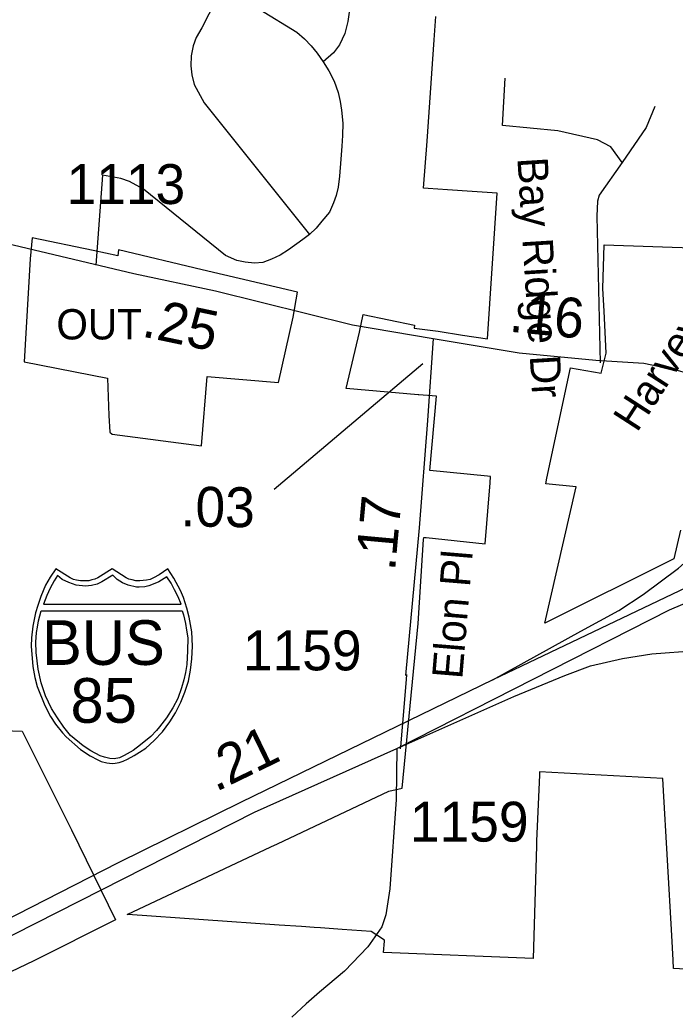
# Model space of a CAD drawing. Extents: x 1662474 to 1856135, y 779280 to 917889.
# Drawn here: x 1719678 to 1721731, y 803792 to 806900 of the extents above; entities that cross this region are included whole.
import ezdxf

# ---------------------------------------------------------------- set-up
doc = ezdxf.new("R2010")
doc.units = 0
for name, color, linetype in [('Exist Boundary Political City Limit New', 7, 'Continuous'), ('Exist Boundary Political City Limit New Hole', 7, 'Continuous'), ('Exist Road Non-System Type 51', 7, 'Continuous'), ('Exist Road Non-System Type 51 Label', 7, 'Continuous'), ('Exist Road Primary Interstate Divided Center Attributed', 7, 'Continuous'), ('Exist Road Primary Interstate Mileage Hundredths English Label', 7, 'Continuous'), ('Exist Road Primary Interstate Ramp 1 Lane Attributed', 7, 'Continuous'), ('Exist Road Primary Interstate Shield CELL', 7, 'Continuous'), ('Exist Road Primary Interstate Shield Number Label', 7, 'Continuous'), ('Exist Road Secondary Mileage Hundredths English Label', 7, 'Continuous'), ('Exist Road Secondary Mileage Tenths English Label', 7, 'Continuous'), ('Exist Road Secondary Type 51 Attributed', 7, 'Continuous'), ('Exist Road Secondary Type 51 Label', 7, 'Continuous'), ('Exist Road Secondary Type 51 Number Label', 7, 'Continuous'), ('Map Preparation Boundary City Limit Buffer Line', 7, 'Continuous')]:
    doc.layers.add(name, color=color, linetype=linetype)

msp = doc.modelspace()

# ---------------------------------------------------------------- linework, layer by layer
at = {"layer": 'Exist Boundary Political City Limit New'}
for points in [[(1721173.6, 806356.1), (1721094.4, 806361.4), (1721017.2, 806366.7), (1720957, 806370.8), (1720942.1, 806372.2), (1720953.6, 806519.4), (1720967.9, 806731.8), (1720975.4, 806837.1), (1720980.6, 806910.2)], [(1722137.9, 803903.6), (1721725.5, 803926.3), (1721724.1, 803951.8), (1721719.8, 804029), (1721692.8, 804502.2), (1721691.6, 804521.8), (1721305.9, 804542.8), (1721305.4, 804533.2), (1721296.5, 804325.5), (1721296.4, 804322.4), (1721296, 804310.5), (1721285.6, 803957.2), (1720816.9, 803975.8), (1720820.4, 804012.2), (1720820.6, 804014.4), (1720778, 804042.1), (1720687, 804048.5), (1720619.2, 804053.2), (1720599.4, 804054.6), (1720560.4, 804057.4), (1720490.5, 804062.2), (1720015.6, 804095.6), (1720013.9, 804095.7), (1720464.4, 804307.7), (1720484.8, 804317.2), (1720834.2, 804481.7), (1720875.6, 804490.9), (1720926, 805007.3), (1720939.5, 805221.9), (1720942.6, 805271.2), (1720943, 805277.5), (1720950.5, 805276.7), (1721135.8, 805257.6), (1721140.9, 805321.3), (1721147, 805398.5), (1721148.9, 805421.7), (1721151, 805448.7), (1721152.6, 805468.3), (1721142.9, 805469.2), (1720961.9, 805486.9), (1720982.8, 805720.5), (1720928.1, 805724.4), (1720925.9, 805724.6), (1720700.2, 805744.1), (1720741.5, 805920.8), (1720753.4, 805975.6), (1720914, 805942.7), (1720913, 805932.7), (1720988.1, 805924.1), (1721064.2, 805911.5), (1721143.1, 805899.6), (1721173.6, 806356.1)], [(1721747.5, 805300.2), (1721726.5, 805210.4), (1721322.8, 805008), (1721420.6, 805435.9), (1721325.1, 805445.7), (1721328.8, 805462.7), (1721402.4, 805808.8), (1721499.1, 805792.4), (1721514.5, 805855.2), (1721509.1, 805964.4), (1721508, 805985.9), (1721504.5, 806057.5), (1721508.1, 806194.1), (1721966.2, 806178.8)], [(1718688.2, 803734.9), (1719498.1, 804134.4), (1718974.8, 804180.6), (1718997.4, 804506.2), (1719004, 804695.2), (1719269.6, 804685.4), (1719533.6, 804675.3), (1719685.4, 804669.5), (1719839.9, 804360.9), (1719976.9, 804078.1), (1719721.5, 803950.2), (1719294.9, 803746.4)]]:
    msp.add_lwpolyline(points, dxfattribs=at)
at = {"layer": 'Exist Boundary Political City Limit New Hole'}
msp.add_lwpolyline([(1719952, 805775.9), (1719956.2, 805659.5), (1719959.2, 805607.2), (1719966.6, 805601.2), (1720246.6, 805564.1), (1720264.6, 805781.8), (1720487.8, 805762.5), (1720534.1, 805967.9), (1720547.9, 806046.1), (1720249.2, 806116.4), (1719986.4, 806178.3), (1719985.1, 806159.8), (1719907, 806176.2), (1719716.5, 806215.9), (1719709.8, 806150.5), (1719690.9, 805828.1), (1719952, 805775.9)], dxfattribs=at)
at = {"layer": 'Exist Road Non-System Type 51'}
for p, q in [((1720889.1, 804847.4), (1720887.8, 804831.4)), ((1720887.8, 804831.4), (1720875.1, 804682)), ((1720875.1, 804682), (1720870.1, 804621.1))]:
    msp.add_line(p, q, dxfattribs=at)
for points in [[(1720515.4, 807450.8), (1720653.4, 807336.2), (1720681.5, 807302.4), (1720697.5, 807276.2), (1720708.5, 807252.4), (1720719.2, 807218.7), (1720724, 807192.8), (1720710.1, 806930.5), (1720705.1, 806894), (1720695.6, 806856.2), (1720678.9, 806821.1), (1720660.5, 806796.2), (1720628.4, 806768.1)], [(1720314, 807004.5), (1720247.6, 806874.4), (1720230.6, 806843.9), (1720221.1, 806817.7), (1720214.9, 806786.4), (1720213.5, 806754.9), (1720216.4, 806726.9), (1720224.2, 806696.7), (1720255.5, 806639.2), (1720585.1, 806226.9)], [(1720314, 807004.5), (1720545.8, 806861), (1720569.4, 806839.8), (1720589.9, 806818.4), (1720609.2, 806795.6), (1720628.4, 806768.1)], [(1720628.4, 806768.1), (1720645.5, 806740), (1720662.4, 806707.2), (1720675.4, 806672.2), (1720680.9, 806643.7), (1720685.4, 806616.1), (1720689.6, 806575.4), (1720688.9, 806537.1), (1720686.8, 806503.2), (1720683, 806463.1), (1720679.4, 806409.9), (1720674.9, 806374.7), (1720668.9, 806349.4), (1720660.1, 806325.6), (1720648.1, 806297.2), (1720624.2, 806268.1), (1720606.1, 806246.9), (1720585.1, 806226.9)], [(1721564.6, 806452.1), (1721529.2, 806501.4), (1721487.8, 806523.7), (1721363.6, 806551.2), (1721189.6, 806567.9), (1721198, 806716.6)], [(1721666.8, 806628.4), (1721639.4, 806562.2), (1721564.6, 806452.1)], [(1721564.6, 806452.1), (1721493, 806349.9), (1721487.5, 806330.9), (1721484.9, 806283.9), (1721495.6, 805824.2)], [(1720585.1, 806226.9), (1720564.6, 806211.4), (1720519.2, 806178.4), (1720493.5, 806162.4), (1720466.5, 806148.9), (1720438.6, 806139.2), (1720412.6, 806137.1), (1720383.4, 806139.8), (1720357.9, 806145.2), (1720321.6, 806160.8), (1720064.9, 806368.9), (1720021.4, 806393.2), (1719994.4, 806402.4), (1719936.4, 806412.9), (1719915.4, 806130.2)], [(1720870.1, 804621.1), (1720869.7, 804615)]]:
    msp.add_lwpolyline(points, dxfattribs=at)
at = {"layer": 'Exist Road Primary Interstate Divided Center Attributed'}
for points in [[(1722330.3, 805407), (1722186.6, 805332.3), (1721766.7, 805120.7), (1721159.6, 804831)], [(1720858.9, 804615.4), (1721713.2, 805050.4), (1721754.9, 805068.5), (1721854.3, 805114.4), (1722372.7, 805371.9)], [(1721159.6, 804831), (1720371, 804447.9), (1719985.3, 804257.2), (1719529, 804024.4), (1719223, 803873.5), (1718752.7, 803628.3), (1718585.1, 803541), (1718467.1, 803468.6)], [(1718437.4, 803380.4), (1718560.3, 803462.7), (1718798.4, 803604.1), (1719011.6, 803703.7), (1719282.9, 803844.8), (1719520.9, 803963.7), (1720413, 804416.2), (1720858.9, 804615.4)]]:
    msp.add_lwpolyline(points, dxfattribs=at)
at = {"layer": 'Exist Road Primary Interstate Ramp 1 Lane Attributed'}
for points in [[(1721159.6, 804831), (1721435.7, 804983.7), (1721554.5, 805048.2), (1721630.9, 805098), (1721740.7, 805180.7), (1721849.3, 805276.8), (1721991.4, 805435.3), (1722069.5, 805543.9), (1722105.7, 805586.9)], [(1720858.9, 804615.4), (1721225.8, 804778.9), (1721385.4, 804844.6), (1721465.7, 804875.1), (1721565.3, 804897.7), (1721658.1, 804912.4), (1721796.2, 804922.6), (1721910.5, 804917), (1722055.9, 804898.9), (1722143, 804889.8), (1722198.5, 804888.7), (1722257.3, 804892.1), (1722310.5, 804904.5), (1722360.3, 804923.8), (1722466.1, 804975.8), (1722528.3, 805020), (1722646, 805147.8)]]:
    msp.add_lwpolyline(points, dxfattribs=at)
at = {"layer": 'Exist Road Primary Interstate Shield CELL'}
for points in [[(1719966.5, 804568.6), (1719975.9, 804569.5), (1719988.7, 804572), (1720001.1, 804576.1), (1720015.2, 804582.3), (1720036, 804593.9), (1720052.8, 804603.7), (1720072.1, 804616.7), (1720098.2, 804640.4), (1720124.3, 804667.8), (1720147.3, 804698.8), (1720165.5, 804727.9), (1720181.6, 804761), (1720195, 804791.9), (1720205.7, 804827.2), (1720212.7, 804861.5), (1720216.3, 804897.2), (1720218.7, 804936.8), (1720216, 804981.3), (1720208.3, 805026.9), (1720201, 805055.2), (1720190, 805089.1), (1720181, 805110.8), (1720160.1, 805149.3), (1720141.4, 805178.9), (1720114.2, 805159.7), (1720096.4, 805150.3), (1720085.6, 805145.4), (1720074.4, 805143.2), (1720053.9, 805140.7), (1720041, 805141.3), (1720029.1, 805144), (1720018.9, 805146.2), (1720010.7, 805150.3), (1719966.5, 805178.9), (1719922.2, 805150.3), (1719912.9, 805146), (1719903.4, 805144), (1719894.3, 805141.5), (1719879.1, 805140.7), (1719867.5, 805141.1), (1719855.7, 805143.2), (1719846.3, 805145.2), (1719835.8, 805150.3), (1719790.7, 805178.9), (1719772.9, 805153.1), (1719758.5, 805127.7), (1719743.1, 805091.8), (1719733.6, 805064), (1719726.8, 805041.1), (1719718.4, 804999.1), (1719714.1, 804962.6), (1719713.4, 804936.8), (1719718.1, 804872.2), (1719725.1, 804837.9), (1719732.4, 804810.1), (1719756.2, 804750.1), (1719774.2, 804716.4), (1719789.6, 804692.3), (1719811.2, 804665.1), (1719822.9, 804652.1), (1719867.7, 804613), (1719897.6, 804592.5), (1719921.5, 804579.6), (1719932.7, 804575.4), (1719950.3, 804570.5)], [(1719796, 805158.1), (1719785.1, 805141.2), (1719772.4, 805118.4), (1719762.2, 805094.7), (1719751.9, 805068.5), (1720183.4, 805068.4), (1720173.4, 805090.8), (1720162.6, 805113.3), (1720151.4, 805133.9), (1720137.7, 805153.8), (1720113.5, 805138.5), (1720095.8, 805130.2), (1720081.7, 805125.3), (1720069.7, 805122.6), (1720051.1, 805121.1), (1720042.8, 805121.6), (1720016.8, 805127.5), (1719999.3, 805134.7), (1719982.6, 805145.8), (1719969, 805158.6), (1719934.8, 805137.9), (1719919.7, 805131.2), (1719902.2, 805126.7), (1719883.2, 805124.3), (1719853.7, 805127.5), (1719830.7, 805135.5), (1719810.8, 805145.8)], [(1720186, 805047.1), (1720190.6, 805034.9), (1720197, 805007.8), (1720200.3, 804987), (1720203.7, 804963), (1720202.5, 804921.9), (1720200.5, 804879.3), (1720196.6, 804854.1), (1720191.4, 804831.1), (1720184.2, 804805.7), (1720172.7, 804771.9), (1720156.8, 804743.2), (1720136.9, 804711.4), (1720115.4, 804683.5), (1720106.1, 804671.9), (1720088.4, 804653.3), (1720056.2, 804627.4), (1720032.7, 804609.8), (1720004.5, 804593.2), (1719990.2, 804586.8), (1719973.5, 804583.3), (1719959.8, 804584.3), (1719943.2, 804588.7), (1719929.7, 804592.4), (1719900.3, 804608.3), (1719876.4, 804624.2), (1719836.7, 804656.9), (1719815.2, 804682), (1719795.2, 804711.4), (1719777.3, 804741.5), (1719758.2, 804781.1), (1719744.8, 804821), (1719735, 804864.1), (1719728.4, 804916.7), (1719727.7, 804948.8), (1719729.6, 804979.7), (1719732.5, 804995.8), (1719736.5, 805015.9), (1719744.3, 805046.9)]]:
    msp.add_lwpolyline(points, close=True, dxfattribs=at)
at = {"layer": 'Exist Road Secondary Mileage Tenths English Label'}
msp.add_line((1720940, 805821.7), (1720474.7, 805427.6), dxfattribs=at)
at = {"layer": 'Exist Road Secondary Type 51 Attributed'}
for points in [[(1717795.3, 807246.4), (1717845.9, 807234.3), (1717923, 807212), (1718024.3, 807160.9), (1718483.2, 806892.8), (1719047.9, 806492.2), (1719234.7, 806349.6), (1719334.2, 806284), (1719424, 806251), (1719532.3, 806223.3), (1720034.7, 806104.1), (1720290.4, 806050.2), (1720719.4, 805943.4), (1720972.9, 805900.4)], [(1720972.9, 805900.4), (1720955.3, 805643.5), (1720928.2, 805307.4), (1720885.7, 804844.6)], [(1720972.9, 805900.4), (1721242.2, 805856.2), (1721481.8, 805832.9), (1721632.1, 805823.4), (1721737.3, 805801.9), (1721821.6, 805775.9)], [(1720858.9, 804615.4), (1720856.3, 804455.3), (1720837.1, 804175.7), (1720824.6, 804094.3), (1720812.2, 804056.9), (1720767.5, 803994.1), (1720694.9, 803917.9), (1720616.9, 803852.4), (1720574.3, 803815.2), (1720529.7, 803773.3)]]:
    msp.add_lwpolyline(points, dxfattribs=at)
at = {"layer": 'Map Preparation Boundary City Limit Buffer Line'}
for points in [[(1721173.6, 806356.1), (1721094.4, 806361.4), (1721017.2, 806366.7), (1720957, 806370.8), (1720942.1, 806372.2), (1720953.6, 806519.4), (1720967.9, 806731.8), (1720975.4, 806837.1), (1720980.6, 806910.2)], [(1722137.9, 803903.6), (1721725.5, 803926.3), (1721724.1, 803951.8), (1721719.8, 804029), (1721692.8, 804502.2), (1721691.6, 804521.8), (1721305.9, 804542.8), (1721305.4, 804533.2), (1721296.5, 804325.5), (1721296.4, 804322.4), (1721296, 804310.5), (1721285.6, 803957.2), (1720816.9, 803975.8), (1720820.4, 804012.2), (1720820.6, 804014.4), (1720778, 804042.1), (1720687, 804048.5), (1720619.2, 804053.2), (1720599.4, 804054.6), (1720560.4, 804057.4), (1720490.5, 804062.2), (1720015.6, 804095.6), (1720013.9, 804095.7), (1720464.4, 804307.7), (1720484.8, 804317.2), (1720834.2, 804481.7), (1720875.6, 804490.9), (1720926, 805007.3), (1720939.5, 805221.9), (1720942.6, 805271.2), (1720943, 805277.5), (1720950.5, 805276.7), (1721135.8, 805257.6), (1721140.9, 805321.3), (1721147, 805398.5), (1721148.9, 805421.7), (1721151, 805448.7), (1721152.6, 805468.3), (1721142.9, 805469.2), (1720961.9, 805486.9), (1720982.8, 805720.5), (1720928.1, 805724.4), (1720925.9, 805724.6), (1720700.2, 805744.1), (1720741.5, 805920.8), (1720753.4, 805975.6), (1720914, 805942.7), (1720913, 805932.7), (1720988.1, 805924.1), (1721064.2, 805911.5), (1721143.1, 805899.6), (1721173.6, 806356.1)], [(1719952, 805775.9), (1719956.2, 805659.5), (1719959.2, 805607.2), (1719966.6, 805601.2), (1720246.6, 805564.1), (1720264.6, 805781.8), (1720487.8, 805762.5), (1720534.1, 805967.9), (1720547.9, 806046.1), (1720249.2, 806116.4), (1719986.4, 806178.3), (1719985.1, 806159.8), (1719907, 806176.2), (1719716.5, 806215.9), (1719709.8, 806150.5), (1719690.9, 805828.1), (1719952, 805775.9)], [(1721747.5, 805300.2), (1721726.5, 805210.4), (1721322.8, 805008), (1721420.6, 805435.9), (1721325.1, 805445.7), (1721328.8, 805462.7), (1721402.4, 805808.8), (1721499.1, 805792.4), (1721514.5, 805855.2), (1721509.1, 805964.4), (1721508, 805985.9), (1721504.5, 806057.5), (1721508.1, 806194.1), (1721966.2, 806178.8)], [(1718688.2, 803734.9), (1719498.1, 804134.4), (1718974.8, 804180.6), (1718997.4, 804506.2), (1719004, 804695.2), (1719269.6, 804685.4), (1719533.6, 804675.3), (1719685.4, 804669.5), (1719839.9, 804360.9), (1719976.9, 804078.1), (1719721.5, 803950.2), (1719294.9, 803746.4)]]:
    msp.add_lwpolyline(points, dxfattribs=at)

# ---------------------------------------------------------------- texts
at = {"layer": 'Exist Boundary Political City Limit New Hole'}
msp.add_text('OUT', height=95, dxfattribs=at).set_placement((1719792.1, 805897.8))
at = {"layer": 'Exist Road Non-System Type 51 Label'}
msp.add_text('Bay Ridge Dr', height=95, rotation=273.5743, dxfattribs=at).set_placement((1721236.2, 806466.3))
at = {"layer": 'Exist Road Primary Interstate Mileage Hundredths English Label'}
msp.add_text('.21', height=125, rotation=25.9057, dxfattribs=at).set_placement((1720291.4, 804478.4))
at = {"layer": 'Exist Road Primary Interstate Shield Number Label'}
for s, p in [('BUS', (1719747, 804877.6)), ('85', (1719836.4, 804696.3))]:
    msp.add_text(s, height=140, dxfattribs=at).set_placement(p)
at = {"layer": 'Exist Road Secondary Mileage Hundredths English Label'}
for s, rotation, p in [('.16', 354.4355, (1721208.1, 805922.4)), ('.25', 348.0988, (1720056.3, 805907.9)), ('.03', 359.2159, (1720180.7, 805312)), ('.17', 84.7614, (1720852.8, 805169.7))]:
    msp.add_text(s, height=125, rotation=rotation, dxfattribs=at).set_placement(p)
at = {"layer": 'Exist Road Secondary Type 51 Label'}
for s, rotation, p in [('Harvey Rd', 57.1388, (1721611.2, 805603.7)), ('Elon Pl', 85.2515, (1721063.5, 804831.5))]:
    msp.add_text(s, height=95, rotation=rotation, dxfattribs=at).set_placement(p)
at = {"layer": 'Exist Road Secondary Type 51 Number Label'}
for s, p in [('1113', (1719824, 806322.2)), ('1159', (1720376.5, 804860.5)), ('1159', (1720899.6, 804323.8))]:
    msp.add_text(s, height=125, dxfattribs=at).set_placement(p)

doc.saveas('drawing.dxf')
